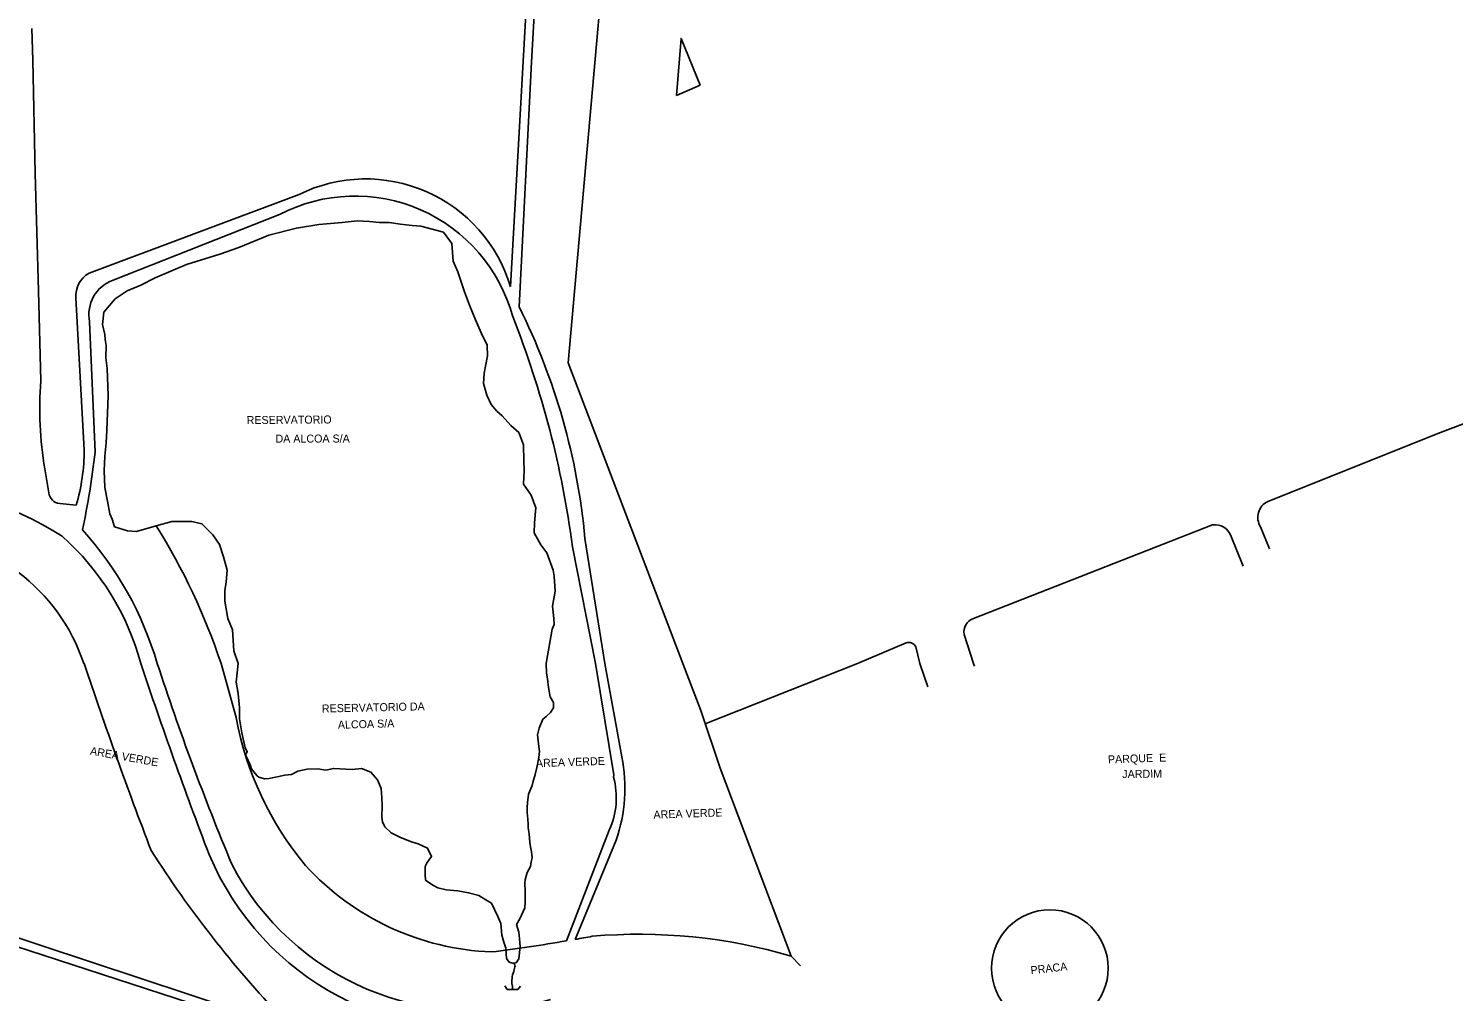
# Model space of a CAD drawing. Extents: x 325899 to 363134, y 7578590 to 7592502.
# Drawn here: x 336176 to 336888, y 7583338 to 7583819 of the extents above; entities that cross this region are included whole.
import ezdxf

# ---------------------------------------------------------------- set-up
doc = ezdxf.new("R2010")
doc.units = 0
for name, color, linetype in [('EDIFEXISTENT', 7, 'Continuous'), ('EDIFFAIXADOM', 7, 'Continuous'), ('EDIFIDENTIF', 7, 'Continuous'), ('EDIFOBRAEXIS', 7, 'Continuous'), ('EDIFOBRAPROJ', 7, 'Continuous')]:
    doc.layers.add(name, color=color, linetype=linetype)

msp = doc.modelspace()

# ---------------------------------------------------------------- linework, layer by layer
at = {"layer": 'EDIFEXISTENT'}
for p, q in [((336414.81, 7583339.06), (336413.62, 7583340.74)), ((336420.14, 7583338.92), (336414.81, 7583339.06)), ((336421.47, 7583340.58), (336420.14, 7583338.92))]:
    msp.add_line(p, q, dxfattribs=at)
at = {"layer": 'EDIFFAIXADOM'}
msp.add_lwpolyline([(336279.29, 7583474.88), (336271.77, 7583501.91)], dxfattribs=at)
for centre, radius, start, end in [((335966.09, 7583400.15), 322.17, 18.41256, 31.98353), ((336114.41, 7583472.76), 93.38, 18.19108, 88.2507), ((338425.64, 7584245.87), 2343.55, 198.50952, 200.93673), ((336439.12, 7583504.75), 162.6, 190.5874, 219.6848), ((336702.29, 7583705.21), 552.02, 212.5213, 223.54067), ((336412.37, 7583491.01), 133.39, 222.48245, 267.67705), ((336381.15, 7583764.44), 406.08, 279.58018, 280.81895), ((336480.66, 7583095.26), 271.33, 73.69554, 94.92282), ((336319.29, 7584074.76), 722.37, 276.97048, 279.97829)]:
    msp.add_arc(centre, radius, start, end, dxfattribs=at)
at = {"layer": 'EDIFOBRAEXIS'}
for points in [[(336474.45, 7583980.27), (336445.29, 7583652.2), (336502.56, 7583501.91)], [(336416.49, 7583690.29), (336431.64, 7583959.92)], [(336435.8, 7583958.59), (336427.05, 7583802.5), (336420.78, 7583680.17)], [(336881.39, 7583617.31), (337654.81, 7583910.54)], [(336181.63, 7583643.19), (336180.55, 7583688.23), (336178.88, 7583746.91), (336177.61, 7583803.46), (336177.11, 7583819.33)], [(336310.76, 7583736.37), (336205.82, 7583696.97)], [(336280.28, 7583501.91), (336278.09, 7583508.33), (336277.44, 7583518.8), (336275.14, 7583524.36), (336273.6, 7583533.12), (336273.73, 7583538.29), (336274.3, 7583542.83), (336274.88, 7583548.66), (336273.01, 7583555.29), (336270.93, 7583561.34), (336267.72, 7583566.24), (336262.21, 7583571.79), (336257.13, 7583572.97), (336247.15, 7583572.88), (336239.35, 7583570.8), (336229.46, 7583567.95), (336225.07, 7583568.26), (336218.55, 7583570.32), (336218.04, 7583571.84), (336217.27, 7583574.01), (336216.2, 7583576.82), (336214.98, 7583583.05), (336213.69, 7583589.91), (336213.31, 7583598.2), (336213.66, 7583605.57), (336214.29, 7583612.24), (336214.73, 7583618.37), (336215.4, 7583635.91), (336214.82, 7583649.31), (336214.11, 7583654.63), (336214.27, 7583660.91), (336213.8, 7583663.95), (336213.74, 7583666.33), (336212.58, 7583671.45), (336213.09, 7583677.61), (336218.79, 7583684.16), (336224.84, 7583688.19), (336231.67, 7583691.05), (336238.8, 7583694.68), (336254.53, 7583701.35), (336271.09, 7583706.6), (336280.65, 7583709.81), (336295.66, 7583716.07), (336309.45, 7583719.57), (336320.67, 7583721.41), (336332.25, 7583722.44), (336339.82, 7583723.2), (336346.06, 7583722.82), (336350.77, 7583722.3), (336355.76, 7583722.34), (336361.42, 7583721.55), (336364.28, 7583721.16), (336367.4, 7583720.92), (336371.63, 7583720.45), (336382.94, 7583717.5), (336387.12, 7583711.89), (336387.79, 7583703.08), (336390.11, 7583697.66), (336393.44, 7583687.69), (336395.97, 7583681.06), (336399.02, 7583673.65), (336401.75, 7583667.17), (336404.79, 7583660.98), (336405.01, 7583655.78), (336403.24, 7583647.01), (336402.93, 7583641.91), (336404.7, 7583636.04), (336406.8, 7583631.36), (336409.57, 7583628.08), (336412.32, 7583625.73), (336416.64, 7583620.83), (336420.66, 7583617.38), (336422.96, 7583611.25), (336423.12, 7583603.17), (336423.24, 7583598.18), (336423.06, 7583591.49), (336426.73, 7583586), (336429.21, 7583579.68), (336428.5, 7583572.25), (336428.39, 7583567.28), (336431.61, 7583561.24), (336434.61, 7583557.17), (336437.86, 7583548.64), (336438.3, 7583545.58), (336438.84, 7583538.08), (336437.45, 7583530.63), (336438.13, 7583524.4), (336438.34, 7583521.43), (336437.34, 7583519.05), (336434.27, 7583501.91)], [(336217.77, 7583693.49), (336300.97, 7583726.3)], [(336199.24, 7583684.71), (336203.36, 7583608.72)], [(336208.81, 7583607.5), (336206.06, 7583672.79)], [(336881.39, 7583617.31), (336795.09, 7583582.89)], [(336185.75, 7583587.27), (336183.61, 7583599.18)], [(336199.38, 7583581.01), (336199.38, 7583581.01), (336191.11, 7583581.94)], [(336647.89, 7583524.41), (336767.38, 7583571.19)], [(336791.48, 7583570.32), (336795.89, 7583559.21)], [(336453.67, 7583564.49), (336463.6, 7583501.91)], [(336776.75, 7583565.41), (336782.76, 7583550.51)], [(336447.47, 7583560.26), (336458.96, 7583501.91)], [(336648, 7583501.91), (336643.28, 7583516.43)], [(336589.9, 7583501.91), (336614.37, 7583512.3)], [(336619.18, 7583510.21), (336621.2, 7583501.91)], [(336280.28, 7583501.91), (336279.29, 7583492.55), (336280.28, 7583486.99), (336280.93, 7583479.79), (336280.93, 7583474.22), (336282.24, 7583467.35), (336283.88, 7583459.83), (336284.86, 7583457.86), (336284.07, 7583456.14), (336284.46, 7583455.32), (336284.83, 7583454.6), (336285.81, 7583452.32), (336286.41, 7583451.5), (336286.76, 7583449.68), (336287.93, 7583447.93), (336289.8, 7583445.71), (336290.63, 7583445.04), (336293.52, 7583444.28), (336295.89, 7583444.52), (336299.8, 7583445.32), (336303.65, 7583446.17), (336306.99, 7583446.52), (336310.08, 7583448.07), (336314.83, 7583449.03), (336320.1, 7583449.3), (336324.11, 7583448.67), (336327.97, 7583449.52), (336337.4, 7583449.01), (336341.99, 7583449.52), (336346.67, 7583447.53), (336349.99, 7583443.73), (336351.85, 7583439.4), (336352.16, 7583434.84), (336352.39, 7583430.86), (336352.12, 7583425.16), (336352.46, 7583422.72), (336353.59, 7583420.3), (336356.8, 7583417.25), (336361.52, 7583414.98), (336367, 7583412.77), (336370.35, 7583411.82), (336375.02, 7583409.63), (336376.99, 7583405.48), (336375.71, 7583403.56), (336374.77, 7583402.46), (336373.82, 7583400.44), (336373.78, 7583397.82), (336373.88, 7583396.39), (336374.04, 7583393.69), (336377.66, 7583391.11), (336380.08, 7583389.75), (336384.31, 7583388.83), (336390.13, 7583388.3), (336395.51, 7583387.35), (336400.73, 7583385.91), (336404.19, 7583383.87), (336406.96, 7583382.19), (336410.08, 7583375.39), (336411.62, 7583372.03), (336412.13, 7583366.19), (336413.2, 7583362.66), (336414.09, 7583359.72), (336414.56, 7583354.47), (336415.88, 7583352.63), (336417.56, 7583352.08), (336419.29, 7583352.27), (336420.63, 7583354.24), (336421.23, 7583360.39), (336421.01, 7583364.34), (336420.61, 7583367.68), (336419.5, 7583371.39), (336421.15, 7583374.26), (336423.59, 7583379.85), (336423.84, 7583382.57), (336423.75, 7583389.49), (336423.67, 7583390.77), (336423.67, 7583392.12), (336423.8, 7583393.84), (336424.8, 7583397.47), (336426.41, 7583400.44), (336426.88, 7583402.73), (336427.24, 7583404.73), (336427.06, 7583407.71), (336426.44, 7583410.22), (336426.18, 7583412.38), (336425.79, 7583416.79), (336425.39, 7583419.86), (336425.36, 7583421.51), (336425.07, 7583424.09), (336424.75, 7583427.53), (336424.77, 7583429.95), (336424.94, 7583432.41), (336425.44, 7583436.63), (336427.35, 7583441.02), (336427.57, 7583442.42), (336428.73, 7583446.4), (336429.75, 7583450.66), (336430.63, 7583454.89), (336431.02, 7583457.94), (336430.47, 7583461.79), (336429.94, 7583466.31), (336430.78, 7583469.63), (336432.61, 7583474.08), (336434.34, 7583475.47), (336436.46, 7583477.42), (336438, 7583479.74), (336438.02, 7583482.41), (336436.32, 7583485.34), (336435.4, 7583489.93), (336434.91, 7583494.22), (336434.48, 7583497.05), (336434.27, 7583501.91), (336434.27, 7583501.91)], [(336458.96, 7583501.91), (336468.08, 7583446.32), (336468.01, 7583445.1)], [(336472.15, 7583455.26), (336463.6, 7583501.91)], [(336502.56, 7583501.91), (336511.6, 7583478.44), (336521.24, 7583449.59), (336556.83, 7583355.67), (336561.44, 7583350.89)], [(336589.9, 7583501.91), (336513.85, 7583471.71)], [(336621.2, 7583501.91), (336625.15, 7583490.26)], [(336648, 7583501.91), (336648.49, 7583500.57)], [(336465.88, 7583418.56), (336445.36, 7583365.46), (336444.46, 7583363.32)], [(336448.73, 7583364.03), (336469.29, 7583413.64)], [(336418.08, 7583352.14), (336418.66, 7583351.21), (336418.74, 7583350.8), (336418.66, 7583350.24), (336418.42, 7583349.66), (336418.26, 7583348.95), (336418.07, 7583348.04), (336417.76, 7583347.17), (336417.52, 7583346.36), (336417.31, 7583345.38), (336417.23, 7583344.51), (336417.17, 7583343.7), (336417.16, 7583342.79), (336417.15, 7583342), (336417.34, 7583341.21), (336417.42, 7583340.78), (336417.56, 7583340.21), (336417.54, 7583339.96), (336417.46, 7583339.71), (336417.43, 7583339.61), (336417.32, 7583338.99)]]:
    msp.add_lwpolyline(points, dxfattribs=at)
for centre, radius, start, end in [((336344.14, 7583668.62), 75.52, 16.66905, 116.22924), ((336338.79, 7583653.97), 81.62, 15.13953, 117.60967), ((336211.86, 7583685.83), 12.67, 118.48671, 185.04636), ((336223.8, 7583676.42), 18.1, 109.45436, 191.55101), ((336131.93, 7583535.54), 323.03, 5.14047, 26.59597), ((335968.38, 7583497.17), 483.23, 7.50214, 21.62968), ((336367.43, 7583629.52), 186.31, 175.79111, 189.37331), ((336102.24, 7583609.12), 101.13, 343.86262, 359.77416), ((335810.24, 7583652.67), 401.12, 347.91112, 353.53512), ((336106.57, 7583433.46), 157.46, 57.0143, 90.52132), ((336191.45, 7583587.64), 5.71, 183.77732, 266.57679), ((336798.74, 7583575.04), 8.66, 114.95187, 213.02544), ((336768.77, 7583562.96), 8.35, 17.05416, 99.61169), ((336106.41, 7583468.43), 129.64, 14.96936, 48.50818), ((336076.11, 7583453.98), 170.64, 16.31392, 42.22608), ((336650.1, 7583517.81), 6.95, 108.47819, 191.46638), ((336615.52, 7583508.37), 4.1, 26.7138, 106.3048), ((338454.65, 7584243.87), 2343.55, 198.45711, 200.93673), ((337549.36, 7583931.27), 1378.07, 198.15359, 202.6031), ((336394.37, 7583439.71), 79.32, 340.8149, 11.30655), ((336429.65, 7583434.82), 39.71, 335.83237, 14.99917), ((336397.69, 7583461.93), 143.06, 202.82404, 281.20152), ((336397.87, 7583464.5), 136.12, 207.51308, 286.45765)]:
    msp.add_arc(centre, radius, start, end, dxfattribs=at)
at = {"layer": 'EDIFOBRAPROJ'}
for points in [[(336499.47, 7583785.87), (336501.73, 7583814.39), (336511.26, 7583791.02)], [(336511.26, 7583791.02), (336499.47, 7583785.87)], [(336101.92, 7583388.96), (336157.09, 7583369.08), (336255.91, 7583336.46), (336301.01, 7583321.45), (336302.13, 7583324.93)], [(336335.11, 7583001.91), (336326.95, 7583061.28), (336307.35, 7583201.2), (336300.44, 7583253.92), (336297.48, 7583276.81), (336295.81, 7583288.54), (336295.85, 7583300.74), (336297.82, 7583312.19), (336300.49, 7583317.76), (336102.34, 7583382.22)]]:
    msp.add_lwpolyline(points, dxfattribs=at)
msp.add_circle((336686.14, 7583349.63), 29.18, dxfattribs=at)

# ---------------------------------------------------------------- texts
at = {"layer": 'EDIFIDENTIF'}
for s, rotation, p in [('RESERVATORIO', 0.45324, (336284.58, 7583621.58)), ('DA ALCOA S/A', 0.0859, (336298.98, 7583612.32)), ('RESERVATORIO DA', 1.29438, (336322.22, 7583477.4)), ('ALCOA S/A', 1.55213, (336330.21, 7583469.29)), ('AREA VERDE', 350.03996, (336206.08, 7583456.43)), ('PARQUE  E', 1.93286, (336715.24, 7583451.97)), ('AREA VERDE', 1.87165, (336429.25, 7583450.13)), ('JARDIM', 0.68252, (336722.35, 7583444.65)), ('AREA VERDE', 1.92345, (336488.03, 7583424.35)), ('PRACA', 6.4015, (336676.71, 7583346.56))]:
    msp.add_text(s, height=4, rotation=rotation, dxfattribs=at).set_placement(p)

doc.saveas('drawing.dxf')
